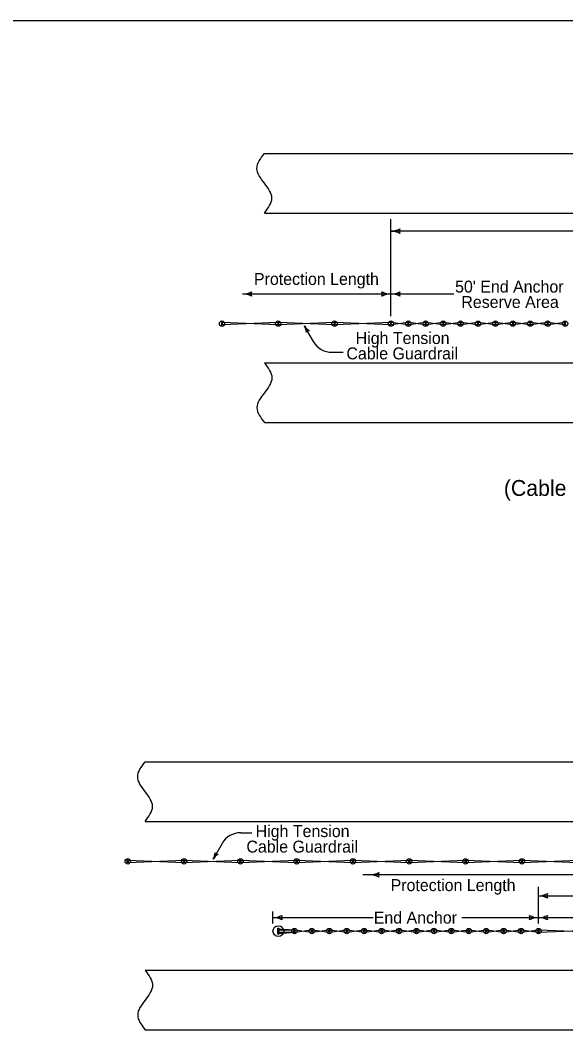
# Model space of a CAD drawing. Extents: x 10133 to 81668, y 7924 to 11018.
# Drawn here: x 11797 to 12346, y 8918 to 9944 of the extents above; entities that cross this region are included whole.
import ezdxf

# ---------------------------------------------------------------- set-up
doc = ezdxf.new("R2010")
doc.units = 0
for name, color, linetype in [('dsnCellElements', 7, 'Continuous'), ('DsnShtRevisedText', 7, 'Continuous'), ('dsnStdDimension', 7, 'Continuous'), ('Level 8', 7, 'Continuous'), ('SheetBorder', 7, 'Continuous')]:
    doc.layers.add(name, color=color, linetype=linetype)

msp = doc.modelspace()

# ---------------------------------------------------------------- linework, layer by layer
at = {"layer": 'dsnCellElements'}
for p, q in [((12055.8, 9639.7), (12000, 9637.5)), ((12055.8, 9637.5), (12000, 9639.7)), ((12112.5, 9639.7), (12056.7, 9637.5)), ((12112.5, 9637.5), (12056.7, 9639.7)), ((12169.2, 9639.7), (12113.4, 9637.5)), ((12169.2, 9637.5), (12113.4, 9639.7)), ((12186.8, 9639.7), (12170.1, 9637.5)), ((12186.8, 9637.5), (12170.1, 9639.7)), ((12204.3, 9639.7), (12187.7, 9637.5)), ((12204.3, 9637.5), (12187.7, 9639.7)), ((12221.8, 9639.7), (12205.2, 9637.5)), ((12221.8, 9637.5), (12205.2, 9639.7)), ((12239.4, 9639.7), (12222.8, 9637.5)), ((12239.4, 9637.5), (12222.8, 9639.7)), ((12256.9, 9639.7), (12240.3, 9637.5)), ((12256.9, 9637.5), (12240.3, 9639.7)), ((12274.5, 9639.7), (12257.9, 9637.5)), ((12274.5, 9637.5), (12257.9, 9639.7)), ((12292, 9639.7), (12275.4, 9637.5)), ((12292, 9637.5), (12275.4, 9639.7)), ((12309.5, 9637.5), (12293, 9639.7)), ((12309.5, 9639.7), (12293, 9637.5)), ((12327.1, 9639.7), (12310.5, 9637.5)), ((12327.1, 9637.5), (12310.5, 9639.7)), ((12344.6, 9639.7), (12328.1, 9637.5)), ((12344.6, 9637.5), (12328.1, 9639.7)), ((11905.1, 9098.1), (11960.9, 9095.9)), ((11905.1, 9095.9), (11960.9, 9098.1)), ((11961.8, 9098.1), (12017.6, 9095.9)), ((11961.8, 9095.9), (12017.6, 9098.1)), ((12018.5, 9098.1), (12074.3, 9095.9)), ((12018.5, 9095.9), (12074.3, 9098.1)), ((12075.2, 9098.1), (12131, 9095.9)), ((12075.2, 9095.9), (12131, 9098.1)), ((12132, 9098.1), (12187.7, 9095.9)), ((12132, 9095.9), (12187.7, 9098.1)), ((12188.7, 9098.1), (12244.4, 9095.9)), ((12188.7, 9095.9), (12244.4, 9098.1)), ((12245.4, 9098.1), (12301.1, 9095.9)), ((12245.4, 9095.9), (12301.1, 9098.1)), ((12302.1, 9098.1), (12357.8, 9095.9)), ((12302.1, 9095.9), (12357.8, 9098.1)), ((12056.3, 9029.2), (12073.1, 9028)), ((12056.3, 9028), (12072.1, 9028)), ((12056.3, 9025.7), (12072.1, 9025.7)), ((12056.3, 9024.5), (12073.1, 9025.7)), ((12073.1, 9028), (12089.7, 9025.7)), ((12073.1, 9025.7), (12089.7, 9028)), ((12090.6, 9028), (12107.2, 9025.7)), ((12090.6, 9025.7), (12107.2, 9028)), ((12108.2, 9028), (12124.8, 9025.7)), ((12108.2, 9025.7), (12124.8, 9028)), ((12125.7, 9028), (12142.3, 9025.7)), ((12125.7, 9025.7), (12142.3, 9028)), ((12143.3, 9028), (12159.9, 9025.7)), ((12143.3, 9025.7), (12159.9, 9028)), ((12160.8, 9028), (12177.4, 9025.7)), ((12160.8, 9025.7), (12177.4, 9028)), ((12178.4, 9025.7), (12194.9, 9028)), ((12178.4, 9028), (12194.9, 9025.7)), ((12195.9, 9028), (12212.5, 9025.7)), ((12195.9, 9025.7), (12212.5, 9028)), ((12213.5, 9028), (12230, 9025.7)), ((12213.5, 9025.7), (12230, 9028)), ((12231, 9028), (12247.6, 9025.7)), ((12231, 9025.7), (12247.6, 9028)), ((12248.5, 9028), (12265.1, 9025.7)), ((12248.5, 9025.7), (12265.1, 9028)), ((12266.1, 9028), (12282.7, 9025.7)), ((12266.1, 9025.7), (12282.7, 9028)), ((12283.6, 9028), (12300.2, 9025.7)), ((12283.6, 9025.7), (12300.2, 9028)), ((12301.2, 9028), (12317.8, 9025.7)), ((12301.2, 9025.7), (12317.8, 9028)), ((12318.7, 9028), (12374.5, 9025.7)), ((12318.7, 9025.7), (12374.5, 9028))]:
    msp.add_line(p, q, dxfattribs=at)
for points in [[(12000, 9637.5), (12000, 9639.7), (11999.1, 9639.7), (11999.1, 9637.5)], [(12056.7, 9637.5), (12056.7, 9639.7), (12055.8, 9639.7), (12055.8, 9637.5)], [(12056.7, 9637.5), (12056.7, 9639.7), (12055.8, 9639.7), (12055.8, 9637.5)], [(12113.4, 9637.5), (12113.4, 9639.7), (12112.5, 9639.7), (12112.5, 9637.5)], [(12113.4, 9637.5), (12113.4, 9639.7), (12112.5, 9639.7), (12112.5, 9637.5)], [(12170.1, 9637.5), (12170.1, 9639.7), (12169.2, 9639.7), (12169.2, 9637.5)], [(12170.1, 9637.5), (12170.1, 9639.7), (12169.2, 9639.7), (12169.2, 9637.5)], [(12187.7, 9637.5), (12187.7, 9639.7), (12186.8, 9639.7), (12186.8, 9637.5)], [(12205.2, 9637.5), (12205.2, 9639.7), (12204.3, 9639.7), (12204.3, 9637.5)], [(12222.8, 9637.5), (12222.8, 9639.7), (12221.8, 9639.7), (12221.8, 9637.5)], [(12240.3, 9637.5), (12240.3, 9639.7), (12239.4, 9639.7), (12239.4, 9637.5)], [(12257.9, 9637.5), (12257.9, 9639.7), (12256.9, 9639.7), (12256.9, 9637.5)], [(12275.4, 9637.5), (12275.4, 9639.7), (12274.5, 9639.7), (12274.5, 9637.5)], [(12293, 9637.5), (12293, 9639.7), (12292, 9639.7), (12292, 9637.5)], [(12310.5, 9637.5), (12310.5, 9639.7), (12309.5, 9639.7), (12309.5, 9637.5)], [(12328.1, 9637.5), (12328.1, 9639.7), (12327.1, 9639.7), (12327.1, 9637.5)], [(12345.6, 9637.5), (12345.6, 9639.7), (12344.6, 9639.7), (12344.6, 9637.5)], [(11904.2, 9095.9), (11904.2, 9098.1), (11905.1, 9098.1), (11905.1, 9095.9)], [(11960.9, 9095.9), (11960.9, 9098.1), (11961.8, 9098.1), (11961.8, 9095.9)], [(11960.9, 9095.9), (11960.9, 9098.1), (11961.8, 9098.1), (11961.8, 9095.9)], [(12017.6, 9095.9), (12017.6, 9098.1), (12018.5, 9098.1), (12018.5, 9095.9)], [(12017.6, 9095.9), (12017.6, 9098.1), (12018.5, 9098.1), (12018.5, 9095.9)], [(12074.3, 9095.9), (12074.3, 9098.1), (12075.2, 9098.1), (12075.2, 9095.9)], [(12074.3, 9095.9), (12074.3, 9098.1), (12075.2, 9098.1), (12075.2, 9095.9)], [(12131, 9095.9), (12131, 9098.1), (12132, 9098.1), (12132, 9095.9)], [(12131, 9095.9), (12131, 9098.1), (12132, 9098.1), (12132, 9095.9)], [(12187.7, 9095.9), (12187.7, 9098.1), (12188.7, 9098.1), (12188.7, 9095.9)], [(12187.7, 9095.9), (12187.7, 9098.1), (12188.7, 9098.1), (12188.7, 9095.9)], [(12244.4, 9095.9), (12244.4, 9098.1), (12245.4, 9098.1), (12245.4, 9095.9)], [(12244.4, 9095.9), (12244.4, 9098.1), (12245.4, 9098.1), (12245.4, 9095.9)], [(12301.1, 9095.9), (12301.1, 9098.1), (12302.1, 9098.1), (12302.1, 9095.9)], [(12301.1, 9095.9), (12301.1, 9098.1), (12302.1, 9098.1), (12302.1, 9095.9)], [(12055.7, 9023.8), (12055.7, 9029.9), (12056.9, 9029.9), (12056.9, 9023.8)], [(12072.1, 9025.7), (12072.1, 9028), (12073.1, 9028), (12073.1, 9025.7)], [(12089.7, 9025.7), (12089.7, 9028), (12090.6, 9028), (12090.6, 9025.7)], [(12107.2, 9025.7), (12107.2, 9028), (12108.2, 9028), (12108.2, 9025.7)], [(12124.8, 9025.7), (12124.8, 9028), (12125.7, 9028), (12125.7, 9025.7)], [(12142.3, 9025.7), (12142.3, 9028), (12143.3, 9028), (12143.3, 9025.7)], [(12159.9, 9025.7), (12159.9, 9028), (12160.8, 9028), (12160.8, 9025.7)], [(12177.4, 9025.7), (12177.4, 9028), (12178.4, 9028), (12178.4, 9025.7)], [(12194.9, 9025.7), (12194.9, 9028), (12195.9, 9028), (12195.9, 9025.7)], [(12212.5, 9025.7), (12212.5, 9028), (12213.5, 9028), (12213.5, 9025.7)], [(12230, 9025.7), (12230, 9028), (12231, 9028), (12231, 9025.7)], [(12247.6, 9025.7), (12247.6, 9028), (12248.5, 9028), (12248.5, 9025.7)], [(12265.1, 9025.7), (12265.1, 9028), (12266.1, 9028), (12266.1, 9025.7)], [(12282.7, 9025.7), (12282.7, 9028), (12283.6, 9028), (12283.6, 9025.7)], [(12300.2, 9025.7), (12300.2, 9028), (12301.2, 9028), (12301.2, 9025.7)], [(12317.8, 9025.7), (12317.8, 9028), (12318.7, 9028), (12318.7, 9025.7)], [(12317.8, 9025.7), (12317.8, 9028), (12318.7, 9028), (12318.7, 9025.7)]]:
    msp.add_lwpolyline(points, close=True, dxfattribs=at)
for centre, radius in [((11999.6, 9638.6), 2.66), ((12056.3, 9638.6), 2.66), ((12056.3, 9638.6), 2.66), ((12113, 9638.6), 2.66), ((12113, 9638.6), 2.66), ((12169.7, 9638.6), 2.66), ((12169.7, 9638.6), 2.66), ((12187.2, 9638.6), 2.66), ((12204.7, 9638.6), 2.66), ((12222.3, 9638.6), 2.66), ((12239.8, 9638.6), 2.66), ((12257.4, 9638.6), 2.66), ((12274.9, 9638.6), 2.66), ((12292.5, 9638.6), 2.66), ((12310, 9638.6), 2.66), ((12327.6, 9638.6), 2.66), ((12345.1, 9638.6), 2.66), ((11904.7, 9097), 2.66), ((11961.4, 9097), 2.66), ((11961.4, 9097), 2.66), ((12018.1, 9097), 2.66), ((12018.1, 9097), 2.66), ((12074.8, 9097), 2.66), ((12074.8, 9097), 2.66), ((12131.5, 9097), 2.66), ((12131.5, 9097), 2.66), ((12188.2, 9097), 2.66), ((12188.2, 9097), 2.66), ((12244.9, 9097), 2.66), ((12244.9, 9097), 2.66), ((12301.6, 9097), 2.66), ((12301.6, 9097), 2.66), ((12056.3, 9026.8), 5.4), ((12072.6, 9026.8), 2.66), ((12090.1, 9026.8), 2.66), ((12107.7, 9026.8), 2.66), ((12125.2, 9026.8), 2.66), ((12142.8, 9026.8), 2.66), ((12160.3, 9026.8), 2.66), ((12177.9, 9026.8), 2.66), ((12195.4, 9026.8), 2.66), ((12213, 9026.8), 2.66), ((12230.5, 9026.8), 2.66), ((12248.1, 9026.8), 2.66), ((12265.6, 9026.8), 2.66), ((12283.2, 9026.8), 2.66), ((12300.7, 9026.8), 2.66), ((12318.3, 9026.8), 2.66), ((12318.3, 9026.8), 2.66)]:
    msp.add_circle(centre, radius, dxfattribs=at)
at = {"layer": 'DsnShtRevisedText'}
for p, q in [((12169.7, 9646.1), (12169.7, 9743.7)), ((12461.1, 9731.7), (12169.7, 9731.7)), ((12146.7, 9668.4), (12020.3, 9668.4)), ((12169.7, 9668.4), (12146.7, 9668.4)), ((12232.9, 9668.4), (12169.7, 9668.4)), ((12091.6, 9620.6), (12082.7, 9636.2)), ((12110.4, 9609.8), (12121.7, 9609.8)), ((12018.5, 9125.8), (12029.8, 9125.8)), ((11999.7, 9115), (11990.8, 9099.4)), ((12177.4, 9083.5), (12141.3, 9083.5)), ((12641.8, 9083.5), (12177.4, 9083.5)), ((12318.3, 9034.4), (12318.3, 9071.3)), ((12318.3, 9062.3), (12475.1, 9062.3)), ((12050.9, 9034.4), (12050.9, 9046.4)), ((12050.9, 9040.4), (12151.8, 9040.4)), ((12241.2, 9040.4), (12318.3, 9040.4)), ((12318.3, 9040.4), (12778.6, 9040.4))]:
    msp.add_line(p, q, dxfattribs=at)
for centre, radius, start, end in [((12169.7, 9750.8), 19.1, 270, 298.0725), ((12169.7, 9712.6), 19.1, 61.9275, 90), ((12185.7, 9731.7), 7.39, 162.2666, 197.7334), ((12020.3, 9687.6), 19.1, 270, 298.0725), ((12036.3, 9668.4), 7.39, 162.2666, 197.7334), ((12153.6, 9668.4), 7.39, 342.2666, 17.7333), ((12169.7, 9687.6), 19.1, 241.9275, 270), ((12169.7, 9687.6), 19.1, 270, 298.0725), ((12185.7, 9668.4), 7.39, 162.2666, 197.7334), ((12020.3, 9649.3), 19.1, 61.9275, 90), ((12169.7, 9649.3), 19.1, 90, 118.0725), ((12169.7, 9649.3), 19.1, 61.9275, 90), ((12071, 9629.4), 13.6, 2.1589, 30.2314), ((12094.5, 9643.1), 13.6, 210.2314, 238.3038), ((12088.5, 9626.4), 5.25, 102.498, 137.9647), ((12110.4, 9631.5), 21.8, 210.2243, 270), ((12018.5, 9104.1), 21.8, 90, 149.7757), ((11979.1, 9106.2), 13.6, 329.7686, 357.8411), ((11996.6, 9109.2), 5.25, 222.0353, 257.502), ((12002.6, 9092.5), 13.6, 121.6962, 149.7686), ((12148.6, 9102.6), 19.1, 270, 298.0725), ((12164.6, 9083.5), 7.39, 162.2666, 197.7334), ((12148.6, 9064.4), 19.1, 61.9275, 90), ((12318.3, 9081.4), 19.1, 270, 298.0725), ((12334.3, 9062.3), 7.39, 162.2666, 197.7334), ((12318.3, 9043.1), 19.1, 61.9275, 90), ((12050.9, 9059.5), 19.1, 270, 298.0725), ((12050.9, 9021.2), 19.1, 61.9275, 90), ((12067, 9040.4), 7.39, 162.2666, 197.7334), ((12302.2, 9040.4), 7.39, 342.2666, 17.7333), ((12318.3, 9059.5), 19.1, 241.9275, 270), ((12318.3, 9021.2), 19.1, 90, 118.0725), ((12318.3, 9059.5), 19.1, 270, 298.0725), ((12318.3, 9021.2), 19.1, 61.9275, 90), ((12334.3, 9040.4), 7.39, 162.2666, 197.7334)]:
    msp.add_arc(centre, radius, start, end, dxfattribs=at)
at = {"layer": 'dsnStdDimension'}
for p, q in [((12042.3, 9810), (12918, 9810)), ((12042.3, 9750), (12918, 9750)), ((12042.3, 9599), (12918, 9599)), ((12042.3, 9539), (12918, 9539)), ((11922.2, 9197.3), (13037.9, 9197.3)), ((11922.2, 9137.3), (13037.9, 9137.3)), ((11922.2, 8987.3), (13037.9, 8987.3)), ((11922.2, 8927.3), (13037.9, 8927.3))]:
    msp.add_line(p, q, dxfattribs=at)
for points in [[(12042.3, 9750), (12049.8, 9765), (12042.3, 9780), (12034.8, 9795), (12042.3, 9810)], [(12042.3, 9599), (12049.8, 9584), (12042.3, 9569), (12034.8, 9554), (12042.3, 9539)], [(11922.2, 9137.3), (11929.7, 9152.3), (11922.2, 9167.3), (11914.7, 9182.3), (11922.2, 9197.3)], [(11922.2, 8987.3), (11929.7, 8972.3), (11922.2, 8957.3), (11914.7, 8942.3), (11922.2, 8927.3)]]:
    msp.add_spline(points, degree=3, dxfattribs=at)
at = {"layer": 'SheetBorder'}
msp.add_lwpolyline([(10132.5, 9944), (13267.5, 9944), (13267.5, 7924), (10132.5, 7924)], close=True, dxfattribs=at)

# ---------------------------------------------------------------- texts
at = {"layer": 'DsnShtRevisedText'}
for s, p in [('Protection Length', (12031.8, 9677.6)), ("50' End Anchor", (12234.3, 9669.9)), ('Reserve Area', (12240.6, 9654.4)), ('High Tension', (12134.2, 9618.1)), ('Cable Guardrail', (12124.9, 9602.6)), ('High Tension', (12033.5, 9121.5)), ('Cable Guardrail', (12024.2, 9105.9)), ('Protection Length', (12169.4, 9067.1)), ('End Anchor', (12152.4, 9034.4))]:
    msp.add_text(s, height=12, dxfattribs=at).set_placement(p)
at = {"layer": 'Level 8'}
msp.add_text('(Cable switches from near side to far side)', height=16, dxfattribs=at).set_placement((12283.4, 9465.1))

doc.saveas('drawing.dxf')
